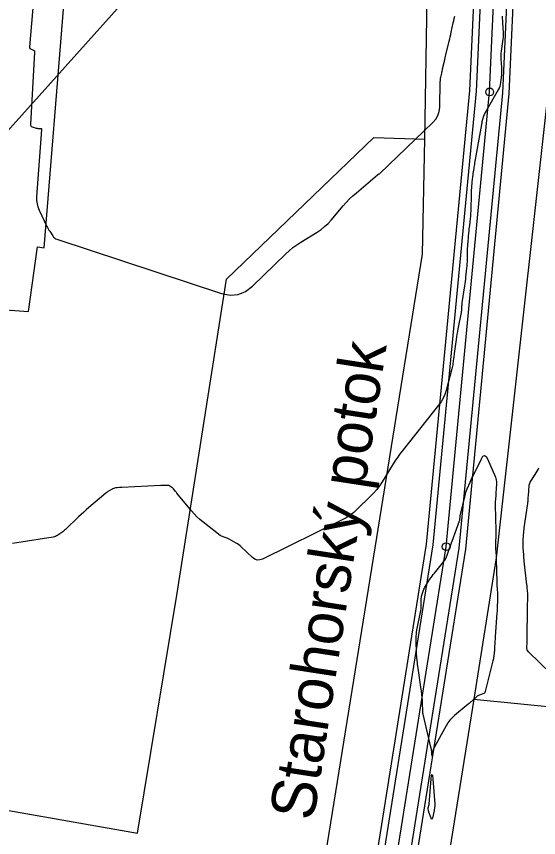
# Model space of a CAD drawing. Extents: x -534481 to -534256, y -1190577 to -1190138.
# Drawn here: x -534363.54 to -534343.69, y -1190311.98 to -1190280.77 of the extents above; entities that cross this region are included whole.
import ezdxf

# ---------------------------------------------------------------- set-up
doc = ezdxf.new("R2010")
doc.units = 0
for name, color, linetype in [('0_kroužky', 7, 'Continuous'), ('30', 7, 'Continuous'), ('31', 7, 'Continuous'), ('_N_osa', 7, 'Continuous'), ('_N_tenká', 7, 'Continuous'), ('_N_text', 7, 'Continuous'), ('Hranice parcel', 7, 'Continuous'), ('Polygon budovy', 7, 'Continuous'), ('Pop  PČ popisy', 7, 'Continuous')]:
    doc.layers.add(name, color=color, linetype=linetype)

msp = doc.modelspace()

# ---------------------------------------------------------------- linework, layer by layer
at = {"layer": '0_kroužky'}
for centre in [(-534345.553, -1190283.64), (-534345.553, -1190283.64), (-534345.553, -1190283.64), (-534345.553, -1190283.64), (-534345.553, -1190283.64), (-534345.553, -1190283.64), (-534347.204, -1190300.921), (-534347.204, -1190300.921), (-534347.204, -1190300.921), (-534347.204, -1190300.921), (-534347.204, -1190300.921), (-534347.204, -1190300.921)]:
    msp.add_circle(centre, 0.15, dxfattribs=at)
at = {"layer": '30'}
msp.add_lwpolyline([(-534362.753, -1190278.515), (-534363.047, -1190281.921), (-534363.046, -1190281.947), (-534363.038, -1190281.97), (-534363.023, -1190281.988), (-534363, -1190282.002), (-534362.897, -1190282.05), (-534362.875, -1190282.065), (-534362.859, -1190282.083), (-534362.851, -1190282.105), (-534362.849, -1190282.132), (-534363.008, -1190284.876), (-534363.006, -1190284.907), (-534362.995, -1190284.932), (-534362.976, -1190284.951), (-534362.948, -1190284.964), (-534362.795, -1190285.011), (-534362.774, -1190285.016), (-534362.753, -1190285.02), (-534362.732, -1190285.023), (-534362.711, -1190285.025), (-534362.625, -1190285.028), (-534362.606, -1190285.032), (-534362.593, -1190285.04), (-534362.586, -1190285.054), (-534362.585, -1190285.073), (-534362.772, -1190287.63), (-534362.773, -1190287.76), (-534362.758, -1190287.887), (-534362.726, -1190288.01), (-534362.677, -1190288.131), (-534362.379, -1190288.748), (-534362.355, -1190288.796), (-534362.33, -1190288.843), (-534362.303, -1190288.889), (-534362.275, -1190288.934), (-534362.16, -1190289.114), (-534362.128, -1190289.155), (-534362.091, -1190289.189), (-534362.049, -1190289.217), (-534362.001, -1190289.237), (-534355.744, -1190291.294), (-534355.419, -1190291.36), (-534355.114, -1190291.337), (-534354.829, -1190291.224), (-534354.566, -1190291.022), (-534353.306, -1190289.795), (-534353.173, -1190289.672), (-534353.034, -1190289.557), (-534352.888, -1190289.45), (-534352.736, -1190289.351), (-534352.109, -1190288.966), (-534351.963, -1190288.868), (-534351.825, -1190288.759), (-534351.697, -1190288.64), (-534351.578, -1190288.51), (-534351.119, -1190287.968), (-534351.002, -1190287.836), (-534350.879, -1190287.708), (-534350.752, -1190287.586), (-534350.619, -1190287.468), (-534349.821, -1190286.792), (-534349.814, -1190286.786), (-534349.807, -1190286.781), (-534349.799, -1190286.776), (-534349.791, -1190286.772), (-534349.759, -1190286.756), (-534349.751, -1190286.752), (-534349.744, -1190286.747), (-534349.737, -1190286.742), (-534349.73, -1190286.736), (-534347.714, -1190284.804), (-534347.603, -1190284.677), (-534347.522, -1190284.535), (-534347.472, -1190284.38), (-534347.452, -1190284.212), (-534347.428, -1190283.243), (-534347.426, -1190283.202), (-534347.422, -1190283.162), (-534347.417, -1190283.122), (-534347.409, -1190283.082), (-534347.375, -1190282.924), (-534347.366, -1190282.884), (-534347.358, -1190282.845), (-534347.349, -1190282.805), (-534347.34, -1190282.765), (-534347.274, -1190282.471), (-534347.26, -1190282.409), (-534347.245, -1190282.347), (-534347.23, -1190282.285), (-534347.215, -1190282.223), (-534347.09, -1190281.712), (-534347.07, -1190281.626), (-534347.05, -1190281.539), (-534347.03, -1190281.452), (-534347.011, -1190281.366), (-534346.936, -1190281.018), (-534346.917, -1190280.932), (-534346.896, -1190280.845), (-534346.875, -1190280.759)], dxfattribs=at)
for points in [[(-534347.696, -1190308.637), (-534347.722, -1190308.717), (-534347.738, -1190308.8), (-534347.743, -1190308.886), (-534347.746, -1190308.799), (-534347.753, -1190308.713), (-534347.765, -1190308.627), (-534347.783, -1190308.543), (-534348.078, -1190307.286), (-534348.087, -1190307.243), (-534348.093, -1190307.199), (-534348.097, -1190307.155), (-534348.099, -1190307.111), (-534348.1, -1190306.933), (-534348.101, -1190306.889), (-534348.103, -1190306.845), (-534348.105, -1190306.8), (-534348.109, -1190306.756), (-534348.128, -1190306.549), (-534348.133, -1190306.5), (-534348.139, -1190306.451), (-534348.145, -1190306.402), (-534348.152, -1190306.353), (-534348.274, -1190305.532), (-534348.283, -1190305.464), (-534348.292, -1190305.395), (-534348.299, -1190305.326), (-534348.305, -1190305.258), (-534348.328, -1190304.982), (-534348.333, -1190304.913), (-534348.336, -1190304.844), (-534348.339, -1190304.775), (-534348.34, -1190304.706), (-534348.343, -1190304.393), (-534348.342, -1190304.318), (-534348.337, -1190304.244), (-534348.328, -1190304.17), (-534348.315, -1190304.096), (-534348.169, -1190303.35), (-534348.16, -1190303.3), (-534348.154, -1190303.25), (-534348.151, -1190303.2), (-534348.15, -1190303.149), (-534348.153, -1190302.927), (-534348.152, -1190302.886), (-534348.148, -1190302.845), (-534348.141, -1190302.805), (-534348.131, -1190302.766), (-534348.083, -1190302.608), (-534348.069, -1190302.569), (-534348.054, -1190302.531), (-534348.035, -1190302.495), (-534348.014, -1190302.459), (-534347.822, -1190302.159), (-534347.782, -1190302.098), (-534347.74, -1190302.038), (-534347.696, -1190301.979), (-534347.651, -1190301.922), (-534347.299, -1190301.487), (-534347.257, -1190301.431), (-534347.221, -1190301.372), (-534347.19, -1190301.309), (-534347.165, -1190301.244), (-534347.075, -1190300.978), (-534347.052, -1190300.911), (-534347.029, -1190300.845), (-534347.005, -1190300.779), (-534346.981, -1190300.713), (-534346.694, -1190299.935), (-534346.689, -1190299.92), (-534346.685, -1190299.905), (-534346.682, -1190299.889), (-534346.681, -1190299.873), (-534346.677, -1190299.809), (-534346.676, -1190299.793), (-534346.674, -1190299.777), (-534346.671, -1190299.761), (-534346.668, -1190299.745), (-534346.489, -1190298.977), (-534346.472, -1190298.911), (-534346.452, -1190298.846), (-534346.43, -1190298.783), (-534346.404, -1190298.72), (-534346.296, -1190298.47), (-534346.269, -1190298.408), (-534346.241, -1190298.346), (-534346.212, -1190298.284), (-534346.183, -1190298.223), (-534345.868, -1190297.582), (-534345.806, -1190297.487), (-534345.746, -1190297.457), (-534345.688, -1190297.49), (-534345.631, -1190297.588), (-534345.332, -1190298.283), (-534345.313, -1190298.336), (-534345.3, -1190298.391), (-534345.294, -1190298.446), (-534345.294, -1190298.502), (-534345.31, -1190298.744), (-534345.316, -1190298.844), (-534345.323, -1190298.945), (-534345.336, -1190299.145), (-534345.338, -1190299.195), (-534345.34, -1190299.246), (-534345.34, -1190299.296), (-534345.339, -1190299.346), (-534345.314, -1190300.305), (-534345.313, -1190300.359), (-534345.314, -1190300.413), (-534345.315, -1190300.467), (-534345.317, -1190300.521), (-534345.329, -1190300.737), (-534345.331, -1190300.791), (-534345.332, -1190300.844), (-534345.331, -1190300.898), (-534345.328, -1190300.952), (-534345.314, -1190301.172), (-534345.31, -1190301.226), (-534345.308, -1190301.281), (-534345.305, -1190301.336), (-534345.304, -1190301.39), (-534345.282, -1190302.264), (-534345.28, -1190302.322), (-534345.278, -1190302.38), (-534345.274, -1190302.438), (-534345.271, -1190302.496), (-534345.254, -1190302.728), (-534345.251, -1190302.786), (-534345.249, -1190302.845), (-534345.249, -1190302.903), (-534345.251, -1190302.961), (-534345.261, -1190303.203), (-534345.263, -1190303.262), (-534345.267, -1190303.322), (-534345.27, -1190303.382), (-534345.274, -1190303.441), (-534345.342, -1190304.352), (-534345.345, -1190304.401), (-534345.348, -1190304.451), (-534345.351, -1190304.5), (-534345.354, -1190304.549), (-534345.363, -1190304.76), (-534345.365, -1190304.802), (-534345.368, -1190304.844), (-534345.372, -1190304.886), (-534345.377, -1190304.928), (-534345.399, -1190305.095), (-534345.405, -1190305.136), (-534345.412, -1190305.178), (-534345.42, -1190305.219), (-534345.43, -1190305.26), (-534345.726, -1190306.429), (-534345.738, -1190306.459), (-534345.755, -1190306.484), (-534345.779, -1190306.504), (-534345.808, -1190306.517), (-534345.939, -1190306.561), (-534345.971, -1190306.574), (-534346.001, -1190306.589), (-534346.029, -1190306.608), (-534346.056, -1190306.629), (-534346.222, -1190306.779), (-534346.259, -1190306.812), (-534346.295, -1190306.844), (-534346.332, -1190306.876), (-534346.37, -1190306.907), (-534346.886, -1190307.34), (-534346.98, -1190307.426), (-534347.064, -1190307.52), (-534347.14, -1190307.621), (-534347.206, -1190307.73), (-534347.66, -1190308.559)], [(-534347.734, -1190311.269), (-534347.746, -1190311.281), (-534347.76, -1190311.271), (-534347.776, -1190311.238), (-534347.862, -1190311.005), (-534347.867, -1190310.99), (-534347.872, -1190310.974), (-534347.875, -1190310.958), (-534347.878, -1190310.942), (-534347.887, -1190310.874), (-534347.888, -1190310.859), (-534347.888, -1190310.845), (-534347.886, -1190310.831), (-534347.882, -1190310.817), (-534347.864, -1190310.761), (-534347.86, -1190310.747), (-534347.857, -1190310.732), (-534347.854, -1190310.718), (-534347.852, -1190310.703), (-534347.771, -1190309.739), (-534347.757, -1190309.615), (-534347.744, -1190309.574), (-534347.73, -1190309.615), (-534347.717, -1190309.739), (-534347.64, -1190310.713), (-534347.64, -1190310.727), (-534347.64, -1190310.74), (-534347.64, -1190310.753), (-534347.641, -1190310.766), (-534347.648, -1190310.834), (-534347.651, -1190310.855), (-534347.656, -1190310.909), (-534347.657, -1190310.919), (-534347.658, -1190310.93), (-534347.66, -1190310.94), (-534347.662, -1190310.951), (-534347.723, -1190311.235)]]:
    msp.add_lwpolyline(points, close=True, dxfattribs=at)
at = {"layer": '31'}
for points in [[(-534345.073, -1190280.761), (-534345.072, -1190280.844), (-534345.069, -1190280.928), (-534345.065, -1190281.012), (-534345.044, -1190281.379), (-534345.041, -1190281.466), (-534345.043, -1190281.553), (-534345.05, -1190281.64), (-534345.061, -1190281.726), (-534345.12, -1190282.096), (-534345.129, -1190282.17), (-534345.134, -1190282.245), (-534345.134, -1190282.32), (-534345.13, -1190282.395), (-534345.102, -1190282.697), (-534345.098, -1190282.771), (-534345.097, -1190282.844), (-534345.1, -1190282.918), (-534345.106, -1190282.991), (-534345.139, -1190283.285), (-534345.151, -1190283.357), (-534345.17, -1190283.427), (-534345.196, -1190283.494), (-534345.23, -1190283.56), (-534345.704, -1190284.383), (-534345.723, -1190284.418), (-534345.74, -1190284.452), (-534345.755, -1190284.488), (-534345.768, -1190284.524), (-534345.834, -1190284.722), (-534345.838, -1190284.733), (-534345.841, -1190284.746), (-534345.844, -1190284.758), (-534345.846, -1190284.77), (-534345.856, -1190284.832), (-534345.862, -1190284.869), (-534345.875, -1190284.947), (-534345.877, -1190284.964), (-534345.88, -1190284.981), (-534345.883, -1190284.999), (-534345.886, -1190285.016), (-534346.124, -1190286.346), (-534346.133, -1190286.396), (-534346.142, -1190286.445), (-534346.15, -1190286.495), (-534346.158, -1190286.545), (-534346.189, -1190286.745), (-534346.196, -1190286.795), (-534346.203, -1190286.845), (-534346.209, -1190286.895), (-534346.214, -1190286.945), (-534346.243, -1190287.229), (-534346.249, -1190287.293), (-534346.253, -1190287.358), (-534346.257, -1190287.422), (-534346.259, -1190287.486), (-534346.274, -1190288.176), (-534346.277, -1190288.243), (-534346.281, -1190288.31), (-534346.286, -1190288.377), (-534346.293, -1190288.444), (-534346.325, -1190288.711), (-534346.333, -1190288.778), (-534346.341, -1190288.845), (-534346.347, -1190288.912), (-534346.354, -1190288.979), (-534346.386, -1190289.338), (-534346.392, -1190289.42), (-534346.398, -1190289.502), (-534346.402, -1190289.585), (-534346.404, -1190289.667), (-534346.411, -1190290.006), (-534346.413, -1190290.09), (-534346.418, -1190290.173), (-534346.424, -1190290.257), (-534346.432, -1190290.341), (-534346.467, -1190290.677), (-534346.476, -1190290.761), (-534346.486, -1190290.844), (-534346.497, -1190290.928), (-534346.509, -1190291.011), (-534346.607, -1190291.656), (-534346.611, -1190291.687), (-534346.614, -1190291.717), (-534346.616, -1190291.748), (-534346.618, -1190291.779), (-534346.622, -1190291.902), (-534346.624, -1190291.933), (-534346.627, -1190291.963), (-534346.631, -1190291.994), (-534346.636, -1190292.024), (-534346.758, -1190292.638), (-534346.778, -1190292.742), (-534346.796, -1190292.845), (-534346.812, -1190292.949), (-534346.827, -1190293.053), (-534346.897, -1190293.582), (-534346.903, -1190293.63), (-534346.91, -1190293.678), (-534346.916, -1190293.726), (-534346.923, -1190293.775), (-534346.949, -1190293.967), (-534346.956, -1190294.015), (-534346.965, -1190294.063), (-534346.976, -1190294.111), (-534346.987, -1190294.158), (-534347.21, -1190294.988), (-534347.258, -1190295.138), (-534347.321, -1190295.281), (-534347.399, -1190295.417), (-534347.491, -1190295.545), (-534348.84, -1190297.237), (-534348.951, -1190297.381), (-534349.058, -1190297.527), (-534349.16, -1190297.677), (-534349.258, -1190297.83), (-534349.644, -1190298.456), (-534349.742, -1190298.604), (-534349.847, -1190298.744), (-534349.961, -1190298.878), (-534350.083, -1190299.005), (-534350.587, -1190299.501), (-534350.717, -1190299.619), (-534350.856, -1190299.725), (-534351.002, -1190299.821), (-534351.157, -1190299.904), (-534354.182, -1190301.392), (-534354.286, -1190301.427), (-534354.385, -1190301.429), (-534354.478, -1190301.398), (-534354.567, -1190301.333), (-534354.996, -1190300.928), (-534355.041, -1190300.887), (-534355.088, -1190300.85), (-534355.137, -1190300.816), (-534355.188, -1190300.784), (-534355.449, -1190300.636), (-534355.476, -1190300.621), (-534355.504, -1190300.608), (-534355.533, -1190300.596), (-534355.563, -1190300.586), (-534355.683, -1190300.551), (-534355.712, -1190300.54), (-534355.74, -1190300.527), (-534355.767, -1190300.512), (-534355.793, -1190300.494), (-534356.455, -1190299.979), (-534356.571, -1190299.883), (-534356.681, -1190299.782), (-534356.785, -1190299.675), (-534356.883, -1190299.561), (-534357.44, -1190298.882), (-534357.455, -1190298.863), (-534357.471, -1190298.844), (-534357.486, -1190298.826), (-534357.501, -1190298.807), (-534357.564, -1190298.729), (-534357.578, -1190298.712), (-534357.594, -1190298.696), (-534357.612, -1190298.681), (-534357.63, -1190298.668), (-534357.705, -1190298.617), (-534357.725, -1190298.606), (-534357.745, -1190298.598), (-534357.766, -1190298.594), (-534357.789, -1190298.593), (-534357.928, -1190298.596), (-534357.959, -1190298.597), (-534357.99, -1190298.598), (-534358.021, -1190298.599), (-534358.052, -1190298.601), (-534359.533, -1190298.675), (-534359.554, -1190298.676), (-534359.575, -1190298.676), (-534359.596, -1190298.677), (-534359.617, -1190298.678), (-534359.71, -1190298.68), (-534359.726, -1190298.681), (-534359.743, -1190298.683), (-534359.759, -1190298.686), (-534359.776, -1190298.689), (-534359.84, -1190298.706), (-534359.856, -1190298.711), (-534359.872, -1190298.717), (-534359.887, -1190298.724), (-534359.902, -1190298.732), (-534360.038, -1190298.812), (-534360.065, -1190298.829), (-534360.092, -1190298.847), (-534360.117, -1190298.866), (-534360.142, -1190298.886), (-534360.786, -1190299.431), (-534360.885, -1190299.517), (-534360.984, -1190299.604), (-534361.08, -1190299.693), (-534361.176, -1190299.784), (-534361.677, -1190300.268), (-534361.711, -1190300.299), (-534361.746, -1190300.329), (-534361.782, -1190300.357), (-534361.819, -1190300.384), (-534361.972, -1190300.487), (-534362.011, -1190300.511), (-534362.052, -1190300.53), (-534362.095, -1190300.544), (-534362.14, -1190300.554), (-534363.689, -1190300.8)], [(-534341.953, -1190306.983), (-534344.077, -1190304.912), (-534344.107, -1190304.876), (-534344.128, -1190304.837), (-534344.139, -1190304.794), (-534344.142, -1190304.748), (-534344.133, -1190304.555), (-534344.131, -1190304.507), (-534344.13, -1190304.459), (-534344.129, -1190304.41), (-534344.128, -1190304.362), (-534344.116, -1190303.309), (-534344.115, -1190303.262), (-534344.114, -1190303.216), (-534344.113, -1190303.17), (-534344.111, -1190303.123), (-534344.103, -1190302.937), (-534344.102, -1190302.891), (-534344.102, -1190302.845), (-534344.103, -1190302.798), (-534344.106, -1190302.752), (-534344.12, -1190302.557), (-534344.123, -1190302.509), (-534344.127, -1190302.461), (-534344.132, -1190302.413), (-534344.137, -1190302.366), (-534344.236, -1190301.477), (-534344.243, -1190301.414), (-534344.248, -1190301.351), (-534344.254, -1190301.288), (-534344.258, -1190301.225), (-534344.275, -1190300.971), (-534344.278, -1190300.908), (-534344.279, -1190300.844), (-534344.279, -1190300.781), (-534344.276, -1190300.718), (-534344.262, -1190300.461), (-534344.258, -1190300.397), (-534344.252, -1190300.333), (-534344.245, -1190300.269), (-534344.237, -1190300.206), (-534344.102, -1190299.277), (-534344.096, -1190299.234), (-534344.091, -1190299.191), (-534344.087, -1190299.148), (-534344.084, -1190299.104), (-534344.072, -1190298.921), (-534344.067, -1190298.844), (-534344.062, -1190298.768), (-534344.053, -1190298.616), (-534344.048, -1190298.579), (-534344.039, -1190298.543), (-534344.025, -1190298.508), (-534344.007, -1190298.475), (-534343.819, -1190298.175), (-534343.782, -1190298.113), (-534343.747, -1190298.051), (-534343.714, -1190297.987), (-534343.684, -1190297.922)]]:
    msp.add_lwpolyline(points, dxfattribs=at)
at = {"layer": '_N_osa'}
msp.add_lwpolyline([(-534409.868, -1190391.439), (-534405.947, -1190382.816), (-534400.873, -1190377.487), (-534393.696, -1190372.718), (-534384.927, -1190365.477), (-534382.631, -1190361.148), (-534355.894, -1190347.823), (-534351.738, -1190342.389), (-534351.577, -1190328.316), (-534347.204, -1190300.921), (-534345.553, -1190283.64), (-534344.682, -1190264.494)], dxfattribs=at)
at = {"layer": '_N_tenká'}
for points in [[(-534409.916, -1190390.337), (-534406.368, -1190382.532), (-534401.196, -1190377.102), (-534393.995, -1190372.316), (-534385.322, -1190365.155), (-534382.997, -1190360.772), (-534356.221, -1190347.427), (-534352.236, -1190342.217), (-534352.076, -1190328.274), (-534347.7, -1190300.857), (-534346.052, -1190283.605), (-534345.255, -1190266.096)], [(-534409.879, -1190389.652), (-534406.578, -1190382.39), (-534401.358, -1190376.909), (-534394.144, -1190372.115), (-534385.52, -1190364.994), (-534383.181, -1190360.584), (-534356.384, -1190347.229), (-534352.485, -1190342.131), (-534352.326, -1190328.253), (-534347.948, -1190300.826), (-534346.301, -1190283.588), (-534345.507, -1190266.125)], [(-534409.363, -1190391.537), (-534405.527, -1190383.099), (-534400.549, -1190377.873), (-534393.398, -1190373.12), (-534384.532, -1190365.799), (-534382.264, -1190361.524), (-534355.568, -1190348.219), (-534351.24, -1190342.56), (-534351.077, -1190328.359), (-534346.708, -1190300.984), (-534345.054, -1190283.675), (-534344.256, -1190266.142)], [(-534409.111, -1190391.586), (-534405.317, -1190383.241), (-534400.388, -1190378.065), (-534393.249, -1190373.321), (-534384.335, -1190365.96), (-534382.081, -1190361.712), (-534355.404, -1190348.417), (-534350.991, -1190342.646), (-534350.828, -1190328.38), (-534346.46, -1190301.016), (-534344.805, -1190283.693), (-534344.008, -1190266.196)]]:
    msp.add_lwpolyline(points, dxfattribs=at)
at = {"layer": '_N_text'}
msp.add_lwpolyline([(-534409.732, -1190388.64), (-534397.101, -1190322.153), (-534346.296, -1190265.502)], dxfattribs=at)
at = {"layer": 'Hranice parcel'}
for p, q in [((-534348.02, -1190285.43), (-534347.63, -1190264.06)), ((-534346.16, -1190306.72), (-534333.95, -1190307.91))]:
    msp.add_line(p, q, dxfattribs=at)
for points in [[(-534341.18, -1190264.8), (-534342.09, -1190272.42), (-534345.3, -1190301.34), (-534346.16, -1190306.72)], [(-534370.75, -1190309.73), (-534358.94, -1190311.81), (-534357.43, -1190302.69), (-534355.55, -1190290.76), (-534349.96, -1190285.37), (-534348.02, -1190285.43)], [(-534353.4, -1190337.34), (-534353.51, -1190323.36), (-534348.1, -1190289.81), (-534348.02, -1190285.43)], [(-534346.16, -1190306.72), (-534349.7, -1190328.83), (-534349.69, -1190337.24)]]:
    msp.add_lwpolyline(points, dxfattribs=at)
at = {"layer": 'Polygon budovy'}
msp.add_lwpolyline([(-534366.14, -1190271.54), (-534367.96, -1190291.63), (-534363.08, -1190291.98), (-534362.74, -1190289.52), (-534362.49, -1190289.56), (-534361.74, -1190280.34), (-534361.6, -1190280.35), (-534360.7, -1190271.99), (-534350.93, -1190272.19), (-534350.88, -1190263.57), (-534365.11, -1190263.3)], close=True, dxfattribs=at)

# ---------------------------------------------------------------- texts
at = {"layer": 'Pop  PČ popisy'}
msp.add_text('Starohorský potok', height=1.7, rotation=81.2569, dxfattribs=at).set_placement((-534352.248, -1190311.375))

doc.saveas('drawing.dxf')
